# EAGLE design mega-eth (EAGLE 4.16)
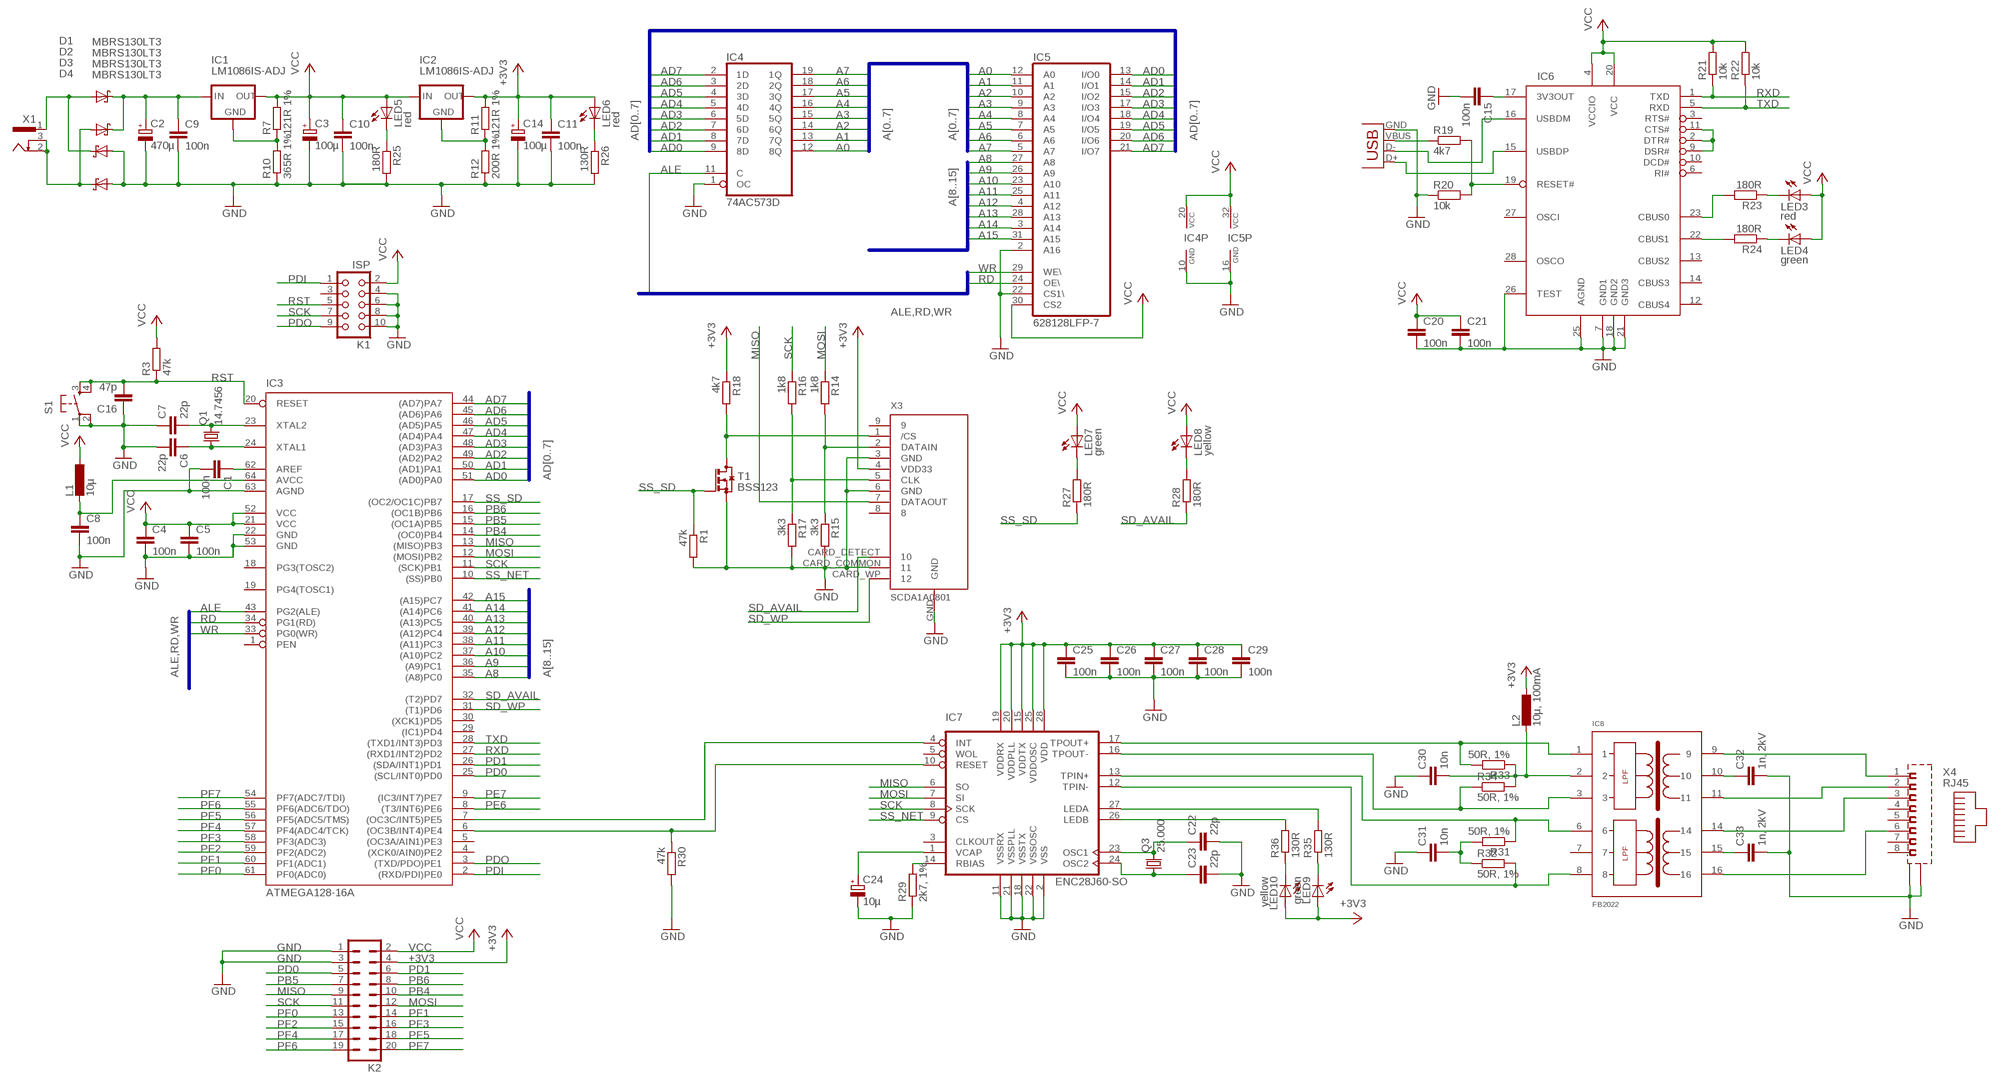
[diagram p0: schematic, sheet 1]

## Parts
C1  100n  C-EUC0805  [C0805]
C2  470µ  CPOL-EU153CLV-0810  [153CLV-0810]
C3  100µ  CPOL-EU153CLV-0605  [153CLV-0605]
C4  100n  C-EUC0805  [C0805]
C5  100n  C-EUC0805  [C0805]
C6  22p  C-EUC0805  [C0805]
C7  22p  C-EUC0805  [C0805]
C8  100n  C-EUC0805  [C0805]
C9  100n  C-EUC0805  [C0805]
C10  100n  C-EUC0805  [C0805]
C11  100n  C-EUC0805  [C0805]
C14  100µ  CPOL-EU153CLV-0605  [153CLV-0605]
C15  100n  C-EUC0805  [C0805]
C16  47p  C-EUC0805  [C0805]
C20  100n  C-EUC0805  [C0805]
C21  100n  C-EUC0805  [C0805]
C22  22p  C-EUC0805  [C0805]
C23  22p  C-EUC0805  [C0805]
C24  10µ  CPOL-EU153CLV-0505  [153CLV-0505]
C25  100n  C-EUC0805  [C0805]
C26  100n  C-EUC0805  [C0805]
C27  100n  C-EUC0805  [C0805]
C28  100n  C-EUC0805  [C0805]
C29  100n  C-EUC0805  [C0805]
C30  10n  C-EUC0805  [C0805]
C31  10n  C-EUC0805  [C0805]
C32  1n, 2kV  C-EU075-032X103  [C075-032X103]
C33  1n, 2kV  C-EU075-032X103  [C075-032X103]
D1  MBRS130LT3  [SMB]
D2  MBRS130LT3  [SMB]
D3  MBRS130LT3  [SMB]
D4  MBRS130LT3  [SMB]
IC1  LM1086IS-ADJ  LM1086TO263  [TO263]
IC2  LM1086IS-ADJ  LM1086TO263  [TO263]
IC3  ATMEGA128-16A  [TQFP64]
IC4  74AC573D  [SO20W]
IC5  628128LFP-7  LP621024CM  [SOP32L]
IC6  FT232RL  [SSOP28DB]
IC7  ENC28J60-SO  [SO28W]
IC8  FB2022  [DIL16/12]
K1  ISP  CON10  [CON10]
K2  MA10-2  [MA10-2]
L1  10µ  L-EUL1206  [L1206]
L2  10µ, 100mA  L-EUL1206  [L1206]
LED3  red  LED3MM  [LED3MM]
LED4  green  LED3MM  [LED3MM]
LED5  red  LED3MM  [LED3MM]
LED6  red  LED3MM  [LED3MM]
LED7  green  LED3MM  [LED3MM]
LED8  yellow  LED3MM  [LED3MM]
LED9  green  LED3MM  [LED3MM]
LED10  yellow  LED3MM  [LED3MM]
Q1  14.7456  CRYTALHC49UP  [HC49UP]
Q3  25.000  CRYTALHC49UP  [HC49UP]
R1  47k  R-EU_R0805  [R0805]
R3  47k  R-EU_R0805  [R0805]
R7  121R 1%  R-EU_R0805  [R0805]
R10  365R 1%  R-EU_R0805  [R0805]
R11  121R 1%  R-EU_R0805  [R0805]
R12  200R 1%  R-EU_R0805  [R0805]
R14  1k8  R-EU_R0805  [R0805]
R15  3k3  R-EU_R0805  [R0805]
R16  1k8  R-EU_R0805  [R0805]
R17  3k3  R-EU_R0805  [R0805]
R18  4k7  R-EU_R0805  [R0805]
R19  4k7  R-EU_R0805  [R0805]
R20  10k  R-EU_R0805  [R0805]
R21  10k  R-EU_R0805  [R0805]
R22  10k  R-EU_R0805  [R0805]
R23  180R  R-EU_R0805  [R0805]
R24  180R  R-EU_R0805  [R0805]
R25  180R  R-EU_R0805  [R0805]
R26  130R  R-EU_R0805  [R0805]
R27  180R  R-EU_R0805  [R0805]
R28  180R  R-EU_R0805  [R0805]
R29  2k7, 1%  R-EU_R0805  [R0805]
R30  47k  R-EU_R0805  [R0805]
R31  50R, 1%  R-EU_R0805  [R0805]
R32  50R, 1%  R-EU_R0805  [R0805]
R33  50R, 1%  R-EU_R0805  [R0805]
R34  50R, 1%  R-EU_R0805  [R0805]
R35  130R  R-EU_R0805  [R0805]
R36  130R  R-EU_R0805  [R0805]
S1  DTSM-6  [DTSM-6]
T1  BSS123  [SOT23]
X1  SCD-014A  [SCD-014-A]
X2  USB-B-H  [USB-B-H]
X3  SCDA1A0801  [SCDA1A0801]
X4  RJ45  [RJ45]

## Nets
+3V3: C11.1 C14.+ C25.1 C26.1 C27.1 C28.1 C29.1 IC2.2(OUT) IC7.15(VDDTX) IC7.19(VDDRX) IC7.20(VDDPLL) IC7.25(VDDOSC) IC7.28(VDD) K2.4 L2.1 LED6.A LED9.A LED10.A R11.2 R18.1 X3.4(VDD33)
A0: IC4.12(8Q) IC5.12(A0)
A1: IC4.13(7Q) IC5.11(A1)
A2: IC4.14(6Q) IC5.10(A2)
A3: IC4.15(5Q) IC5.9(A3)
A4: IC4.16(4Q) IC5.8(A4)
A5: IC4.17(3Q) IC5.7(A5)
A6: IC4.18(2Q) IC5.6(A6)
A7: IC4.19(1Q) IC5.5(A7)
A8: IC3.35((A8)PC0) IC5.27(A8)
A9: IC3.36((A9)PC1) IC5.26(A9)
A10: IC3.37((A10)PC2) IC5.23(A10)
A11: IC3.38((A11)PC3) IC5.25(A11)
A12: IC3.39((A12)PC4) IC5.4(A12)
A13: IC3.40((A13)PC5) IC5.28(A13)
A14: IC3.41((A14)PC6) IC5.3(A14)
A15: IC3.42((A15)PC7) IC5.31(A15)
AD0: IC3.51((AD0)PA0) IC4.9(8D) IC5.13(I/O0)
AD1: IC3.50((AD1)PA1) IC4.8(7D) IC5.14(I/O1)
AD2: IC3.49((AD2)PA2) IC4.7(6D) IC5.15(I/O2)
AD3: IC3.48((AD3)PA3) IC4.6(5D) IC5.17(I/O3)
AD4: IC3.47((AD4)PA4) IC4.5(4D) IC5.18(I/O4)
AD5: IC3.46((AD5)PA5) IC4.4(3D) IC5.19(I/O5)
AD6: IC3.45((AD6)PA6) IC4.3(2D) IC5.20(I/O6)
AD7: IC3.44((AD7)PA7) IC4.2(1D) IC5.21(I/O7)
ALE: IC3.43(PG2(ALE)) IC4.11(C)
GND: C1.2 C2.- C3.- C4.2 C5.2 C6.2 C7.1 C8.2 C9.2 C10.2 C11.2 C14.- C15.2 C16.1 C20.2 C21.2 C22.2 C23.2 C24.- C25.2 C26.2 C27.2 C28.2 C29.2 C30.1 C31.1 C32.2 C33.2 D3.A D4.A IC3.22(GND) IC3.53(GND) IC3.63(AGND) IC4.1(OC) IC4.10(GND) IC5.2(A16) IC5.16(GND) IC5.22(CS1\) IC6.7(GND1) IC6.18(GND2) IC6.21(GND3) IC6.25(AGND) IC6.26(TEST) IC7.2(VSS) IC7.11(VSSRX) IC7.18(VSSTX) IC7.21(VSSPLL) IC7.22(VSSOSC) K1.4 K1.6 K1.8 K1.10 K2.1 K2.3 R1.2 R10.1 R12.1 R15.2 R17.2 R20.1 R25.2 R26.2 R29.1 R30.2 S1.1 S1.2 T1.2(S) X2.GND X3.3(GND) X3.6(GND) X3.CARD_COMMON X3.GND X4.9(GND) X4.10(GND2)
MISO: IC3.13((MISO)PB3) IC7.6(SO) K2.9 X3.7(DATAOUT)
MOSI: IC3.12((MOSI)PB2) IC7.7(SI) K2.12 R14.1
MOSI_3V3: R14.2 R15.1 X3.2(DATAIN)
N$1: IC3.7((OC3C/INT5)PE5) IC7.4(INT)
N$2: IC7.27(LEDA) R35.2
N$3: D1.A D3.C X1.1
N$5: C7.2 IC3.23(XTAL2) Q1.2
N$6: C6.1 IC3.24(XTAL1) Q1.1
N$7: D2.A D4.C X1.2 X1.3
N$9: C1.1 IC3.62(AREF)
N$10: C8.1 IC3.64(AVCC) L1.2
N$11: LED8.K(C) R28.2
N$16: LED7.K(C) R27.2
N$25: C2.+ C9.1 D1.C D2.C IC1.3(IN)
N$29: IC1.1(GND) R7.1 R10.2
N$30: IC2.1(GND) R11.1 R12.2
N$31: IC6.2(DTR#) IC6.9(DSR#) IC6.11(CTS#)
N$32: LED4.K(C) R24.1
N$33: LED3.K(C) R23.1
N$34: IC6.23(CBUS0) R23.2
N$35: LED5.K(C) R25.1
N$36: C15.1 IC6.17(3V3OUT)
N$37: IC6.22(CBUS1) R24.2
N$38: IC6.15(USBDP) X2.D+
N$39: IC6.16(USBDM) X2.D-
N$40: R19.1 X2.VBUS
N$41: IC6.19(RESET#) R19.2 R20.2
N$43: LED6.K(C) R26.1
N$44: C22.1 IC7.23(OSC1) Q3.2
N$47: C23.1 IC7.24(OSC2) Q3.1
N$48: IC7.14(RBIAS) R29.2
N$49: C24.+ IC7.1(VCAP)
N$50: IC7.17(TPOUT+) IC8.1 R33.2
N$51: IC7.16(TPOUT-) IC8.3 R34.1
N$52: IC7.13(TPIN+) IC8.6 R31.1
N$53: IC7.12(TPIN-) IC8.8 R32.2
N$54: C30.2 IC8.2 L2.2 R33.1 R34.2
N$55: C31.2 R31.2 R32.1
N$57: IC7.26(LEDB) R36.2
N$58: LED10.K(C) R36.1
N$59: LED9.K(C) R35.1
N$60: C32.1 IC8.10
N$61: IC3.6((OC3B/INT4)PE4) IC7.10(RESET) R30.1
N$62: IC8.9 X4.1
N$63: IC8.11 X4.2
N$64: IC8.14 X4.3
N$65: IC8.16 X4.6
N$66: C33.1 IC8.15
PB4: IC3.14((OC0)PB4) K2.10
PB5: IC3.15((OC1A)PB5) K2.7
PB6: IC3.16((OC1B)PB6) K2.8
PD0: IC3.25((SCL/INT0)PD0) K2.5
PD1: IC3.26((SDA/INT1)PD1) K2.6
PDI: IC3.2((RXD/PDI)PE0) K1.1
PDO: IC3.3((TXD/PDO)PE1) K1.9
PE6: IC3.8((T3/INT6)PE6)
PE7: IC3.9((IC3/INT7)PE7)
PF0: IC3.61(PF0(ADC0)) K2.13
PF1: IC3.60(PF1(ADC1)) K2.14
PF2: IC3.59(PF2(ADC2)) K2.15
PF3: IC3.58(PF3(ADC3)) K2.16
PF4: IC3.57(PF4(ADC4/TCK)) K2.17
PF5: IC3.56(PF5(ADC5/TMS)) K2.18
PF6: IC3.55(PF6(ADC6/TDO)) K2.19
PF7: IC3.54(PF7(ADC7/TDI)) K2.20
RD: IC3.34(PG1(RD)) IC5.24(OE\)
RST: C16.2 IC3.20(RESET) K1.5 R3.1 S1.3 S1.4
RXD: IC3.27((RXD1/INT2)PD2) IC6.1(TXD) R21.1
SCK: IC3.11((SCK)PB1) IC7.8(SCK) K1.7 K2.11 R16.1
SCK_3V3: R16.2 R17.1 X3.5(CLK)
SD_AVAIL: IC3.32((T2)PD7) R28.1 X3.CARD_DETECT
SD_WP: IC3.31((T1)PD6) X3.CARD_WP
SS_NET: IC3.10((SS)PB0) IC7.9(CS)
SS_SD: IC3.17((OC2/OC1C)PB7) R1.1 R27.1 T1.1(G)
SS_SD_3V3: R18.2 T1.3(D) X3.1(/CS)
TXD: IC3.28((TXD1/INT3)PD3) IC6.5(RXD) R22.1
VCC: C3.+ C4.1 C5.1 C10.1 C20.1 C21.1 IC1.2(OUT) IC2.3(IN) IC3.21(VCC) IC3.52(VCC) IC4.20(VCC) IC5.30(CS2) IC5.32(VCC) IC6.4(VCCIO) IC6.20(VCC) K1.2 K2.2 L1.1 LED3.A LED4.A LED5.A LED7.A LED8.A R3.2 R7.2 R21.2 R22.2
WR: IC3.33(PG0(WR)) IC5.29(WE\)
Unconnected: IC3.1(PEN) IC3.4((XCK0/AIN0)PE2) IC3.5((OC3A/AIN1)PE3) IC3.18(PG3(TOSC2)) IC3.19(PG4(TOSC1)) IC3.29((IC1)PD4) IC3.30((XCK1)PD5) IC5.1(NC) IC6.3(RTS#) IC6.6(RI#) IC6.10(DCD#) IC6.12(CBUS4) IC6.13(CBUS2) IC6.14(CBUS3) IC6.27(OSCI) IC6.28(OSCO) IC7.3(CLKOUT) IC7.5(WOL) IC8.7 K1.3 X3.8 X3.9 X4.4 X4.5 X4.7 X4.8

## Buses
A[8..15]
AD[0..7]
A[0..7]
ALE,RD,WR

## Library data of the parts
C1 C4-C11 C15 C16 C20-C23 C25-C33 = rcl:C-EU: CAPACITOR, European symbol
C2 C3 C14 C24 = rcl:CPOL-EU: POLARIZED CAPACITOR, European symbol
D1-D4 = diode:MBRS130LT3: Schottky Power Rectifier
IC1 IC2 = v-reg-2:LM1086
IC3 = avr:ATMEGA128: MICROCONTROLLER 128 Kbytes FLASH 4 Kbytes SRAM 4 Kbytes EEPROM DUAL USART 8-channel 10 bit ADC
IC4 = 74xx-eu:74*573: 8-bit D latch BUS DRIVER
IC5 = memory:LP621024CM: MEMORY
IC6 = ftdichip-3:FT232RL: USB UART 4th Generation USB UART (USB <-> Serial) Controller
IC7 = microchip-enc28j60:ENC28J60-*: Microchip 10Mbit Eth. contoller with SPI interface
IC8 = fb2022:FB2022: FILTER Bothhand USA, FB2022 10 BaseT Low Pass Filter Transmitter & Receiver http://www.bothhandusa.com Roland Riegel
K1 = con-harting:CON10: CONNECTOR
K2 = con-lstb:MA10-2: PIN HEADER
L1 L2 = rcl:L-EU: INDUCTOR, European symbol
LED3-LED10 = led:LED: LED
Q1 Q3 = crystal:CRYTAL: CRYSTAL
R1 R3 R7 R10-R12 R14-R36 = rcl:R-EU_: RESISTOR, European symbol
S1 = switch-tact:DTSM-6
T1 = transistor-small-signal:BSS123: N-CHANNEL MOS FET
X1 = con-shiua-chyuan:SCD-014A: Power Jack 2.5mm
X2 = con-usb:USB: USB Connectors
X3 = mmc_sd_card:SCDA1A0801
X4 = rj45:RJ45: Reichelt MEBP 8-8G

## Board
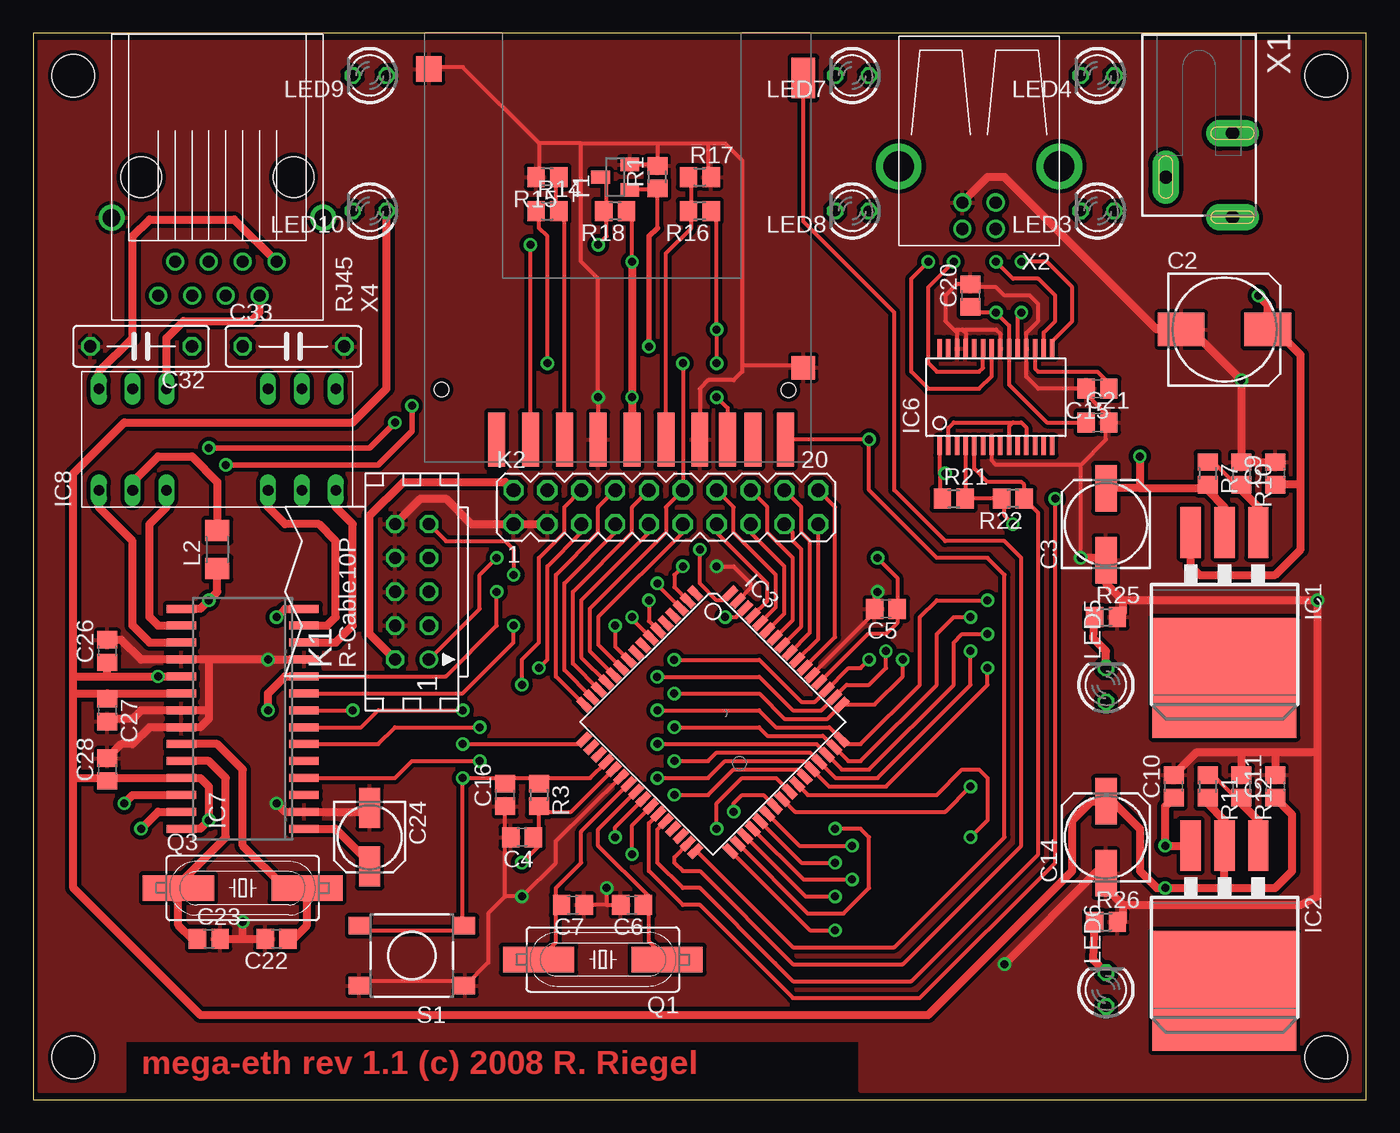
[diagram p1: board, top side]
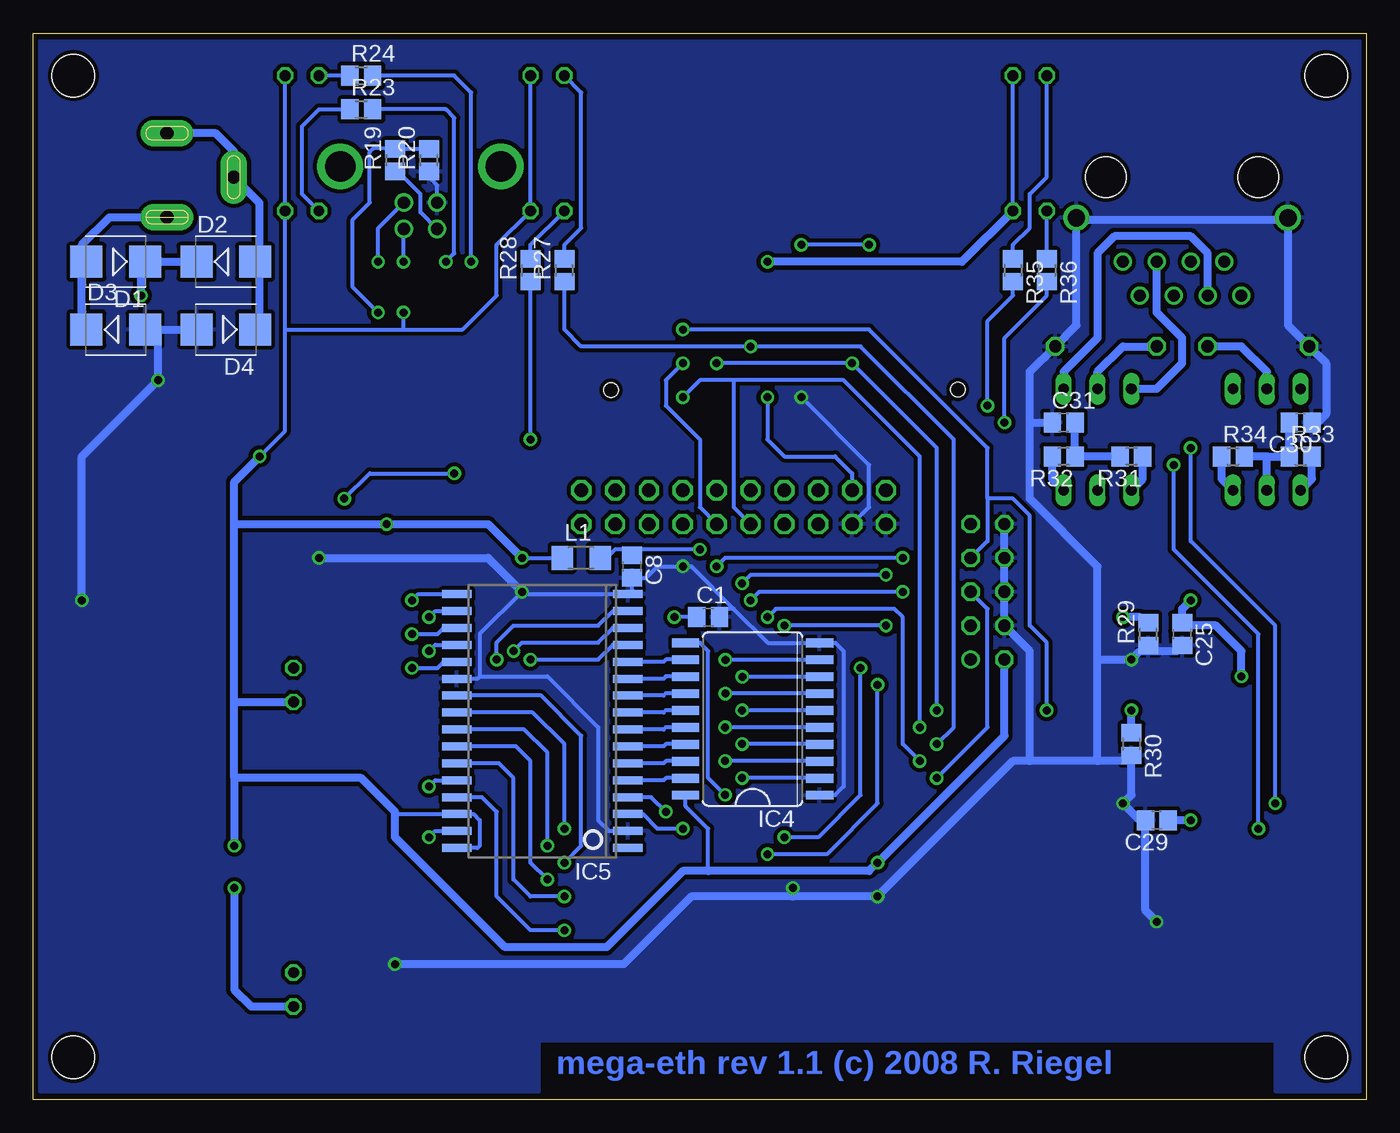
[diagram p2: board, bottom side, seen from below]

Size 100 x 80 mm. Coordinates in mm from the lower left corner, seen from the top.
Outline: 0,0 100,0 100,80 0,80 0,0
Copper layers (1*16): Top 0.035mm / dielectric 1.5mm / Bottom 0.035mm
Design rules "haka_zwilling": minimum track width 8mil, minimum drill 20mil, track to track 8mil, track to pad 8mil, pad to pad 8mil, via to via 8mil, smd to smd 0mil, copper to edge 10mil, drill to drill 10mil, minimum pad ring 8mil, minimum via ring 8mil, stop-mask expansion 4mil, vias tented up to drill 0mil, thermal gap 10mil
Holes 3.2 mm at 3.01,76.83 96.99,3.17 96.99,76.83 3.01,3.17

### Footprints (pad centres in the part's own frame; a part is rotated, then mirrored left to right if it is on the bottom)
C0805 = smd 1.3 x 1.5: 1 -0.85,0; 2 0.85,0
153CLV-0810 = smd 3.5 x 2.5: + 3.25,0; - -3.25,0
153CLV-0605 = smd 3.5 x 1.6: + 2.7,0; - -2.7,0
153CLV-0505 = smd 3 x 1.6: + 2.2,0; - -2.2,0
C075-032X103 = drill 0.914 octagon: 1 -3.81,0; 2 3.81,0
SMB = smd 2.4 x 2.4: A 2.2,0; C -2.2,0
TO263 = smd 1.524 x 3.81: 1 -2.54,-8.255; 2 0,-8.255; 3 2.54,-8.255 | smd 10.8 x 9: 4 0,2.635
TQFP64 = smd 1.194 x 0.559: 1 -7.76,5.905; 2 -7.76,5.118; 3 -7.76,4.331; 4 -7.76,3.543; 5 -7.76,2.756; 6 -7.76,1.968; 7 -7.76,1.181; 8 -7.76,0.394; 9 -7.76,-0.394; 10 -7.76,-1.181; 11 -7.76,-1.968; 12 -7.76,-2.756; 13 -7.76,-3.543; 14 -7.76,-4.331; 15 -7.76,-5.118; 16 -7.76,-5.905; 33 7.76,-5.905; 34 7.76,-5.118; 35 7.76,-4.331; 36 7.76,-3.543; 37 7.76,-2.756; 38 7.76,-1.968; 39 7.76,-1.181; 40 7.76,-0.394; 41 7.76,0.394; 42 7.76,1.181; 43 7.76,1.968; 44 7.76,2.756; 45 7.76,3.543; 46 7.76,4.331; 47 7.76,5.118; 48 7.76,5.905 | smd 0.559 x 1.194: 17 -5.905,-7.76; 18 -5.118,-7.76; 19 -4.331,-7.76; 20 -3.543,-7.76; 21 -2.756,-7.76; 22 -1.968,-7.76; 23 -1.181,-7.76; 24 -0.394,-7.76; 25 0.394,-7.76; 26 1.181,-7.76; 27 1.968,-7.76; 28 2.756,-7.76; 29 3.543,-7.76; 30 4.331,-7.76; 31 5.118,-7.76; 32 5.905,-7.76; 49 5.905,7.76; 50 5.118,7.76; 51 4.331,7.76; 52 3.543,7.76; 53 2.756,7.76; 54 1.968,7.76; 55 1.181,7.76; 56 0.394,7.76; 57 -0.394,7.76; 58 -1.181,7.76; 59 -1.968,7.76; 60 -2.756,7.76; 61 -3.543,7.76; 62 -4.331,7.76; 63 -5.118,7.76; 64 -5.905,7.76
SO20W = smd 0.66 x 2.032: 1 -5.715,-5.029; 2 -4.445,-5.029; 3 -3.175,-5.029; 4 -1.905,-5.029; 5 -0.635,-5.029; 6 0.635,-5.029; 7 1.905,-5.029; 8 3.175,-5.029; 9 4.445,-5.029; 10 5.715,-5.029; 11 5.715,5.029; 12 4.445,5.029; 13 3.175,5.029; 14 1.905,5.029; 15 0.635,5.029; 16 -0.635,5.029; 17 -1.905,5.029; 18 -3.175,5.029; 19 -4.445,5.029; 20 -5.715,5.029
SOP32L = smd 0.6 x 2.2: 1 -9.525,-6.416; 2 -8.255,-6.416; 3 -6.985,-6.416; 4 -5.715,-6.416; 5 -4.445,-6.416; 6 -3.175,-6.416; 7 -1.905,-6.416; 8 -0.635,-6.416; 9 0.635,-6.416; 10 1.905,-6.416; 11 3.175,-6.416; 12 4.445,-6.416; 13 5.715,-6.416; 14 6.985,-6.416; 15 8.255,-6.416; 16 9.525,-6.416; 17 9.525,6.416; 18 8.255,6.416; 19 6.985,6.416; 20 5.715,6.416; 21 4.445,6.416; 22 3.175,6.416; 23 1.905,6.416; 24 0.635,6.416; 25 -0.635,6.416; 26 -1.905,6.416; 27 -3.175,6.416; 28 -4.445,6.416; 29 -5.715,6.416; 30 -6.985,6.416; 31 -8.255,6.416; 32 -9.525,6.416
SSOP28DB = smd 0.348 x 1.397: 1 -4.225,-3.656; 2 -3.575,-3.656; 3 -2.925,-3.656; 4 -2.275,-3.656; 5 -1.625,-3.656; 6 -0.975,-3.656; 7 -0.325,-3.656; 8 0.325,-3.656; 9 0.975,-3.656; 10 1.625,-3.656; 11 2.275,-3.656; 12 2.925,-3.656; 13 3.575,-3.656; 14 4.225,-3.656; 15 4.225,3.656; 16 3.575,3.656; 17 2.925,3.656; 18 2.275,3.656; 19 1.625,3.656; 20 0.975,3.656; 21 0.325,3.656; 22 -0.325,3.656; 23 -0.975,3.656; 24 -1.625,3.656; 25 -2.275,3.656; 26 -2.925,3.656; 27 -3.575,3.656; 28 -4.225,3.656
SO28W = smd 0.6 x 2.2: 1 -8.255,-4.6; 2 -6.985,-4.6; 3 -5.715,-4.6; 4 -4.445,-4.6; 5 -3.175,-4.6; 6 -1.905,-4.6; 7 -0.635,-4.6; 8 0.635,-4.6; 9 1.905,-4.6; 10 3.175,-4.6; 11 4.445,-4.6; 12 5.715,-4.6; 13 6.985,-4.6; 14 8.255,-4.6; 15 8.255,4.6; 16 6.985,4.6; 17 5.715,4.6; 18 4.445,4.6; 19 3.175,4.6; 20 1.905,4.6; 21 0.635,4.6; 22 -0.635,4.6; 23 -1.905,4.6; 24 -3.175,4.6; 25 -4.445,4.6; 26 -5.715,4.6; 27 -6.985,4.6; 28 -8.255,4.6
DIL16/12 = drill 0.8 long: 1 0,0; 2 2.54,0; 3 5.08,0; 6 12.7,0; 7 15.24,0; 8 17.78,0; 9 0,7.62; 10 2.54,7.62; 11 5.08,7.62; 14 12.7,7.62; 15 15.24,7.62; 16 17.78,7.62
CON10 = drill 0.914 round: 1 -5.08,-1.27 | drill 0.914 octagon: 2 -5.08,1.27; 3 -2.54,-1.27; 4 -2.54,1.27; 5 0,-1.27; 6 0,1.27; 7 2.54,-1.27; 8 2.54,1.27; 9 5.08,-1.27; 10 5.08,1.27
MA10-2 = drill 1.016 octagon: 1 -11.43,-1.27; 2 -11.43,1.27; 3 -8.89,-1.27; 4 -8.89,1.27; 5 -6.35,-1.27; 6 -6.35,1.27; 7 -3.81,-1.27; 8 -3.81,1.27; 9 -1.27,-1.27; 10 -1.27,1.27; 11 1.27,-1.27; 12 1.27,1.27; 13 3.81,-1.27; 14 3.81,1.27; 15 6.35,-1.27; 16 6.35,1.27; 17 8.89,-1.27; 18 8.89,1.27; 19 11.43,-1.27; 20 11.43,1.27
L1206 = smd 1.6 x 1.803: 1 -1.422,0; 2 1.422,0
LED3MM = drill 0.813 octagon: A -1.27,0; K 1.27,0
HC49UP = smd 5.334 x 1.93: 1 -4.826,0; 2 4.826,0
R0805 = smd 1.3 x 1.5: 1 -0.85,0; 2 0.85,0
DTSM-6 = smd 1.55 x 1.3: 1 -3.975,2.25; 2 3.975,2.25; 3 -3.975,-2.25; 4 3.975,-2.25
SOT23 = smd 1 x 1.4: 1 -0.95,-1.1; 2 0.95,-1.1; 3 0,1.1
SCD-014-A = drill 1 pad 2 long: 1 -2.5,13.8; 2 -2.5,7.5; 3 2.5,10.8
USB-B-H = drill 0.914 round: D+ 0,1.25; D- 1.981,1.25; GND 0,-1.25; VBUS 1.981,-1.25 | drill 2.286 round: P$1 -2.718,-6.02; P$2 -2.718,6.02
SCDA1A0801 = smd 1.27 x 4.064: 1 6.35,13.97; 2 3.81,13.97; 3 1.27,13.97; 4 -1.27,13.97; 5 -3.81,13.97; 6 -6.35,13.97; 7 -8.433,13.97; 8 -10.338,13.97; 9 8.89,13.97; CARD_DETECT -12.776,13.97 | smd 1.778 x 1.778: CARD_COMMON -14.122,8.585 | smd 1.778 x 3.048: CARD_WP -14.122,-13.157 | smd 1.905 x 1.905: GND 13.97,-13.818 | hole 1.1: 13.005,10.236; -13.005,10.262
RJ45 = drill 0.9 round: 1 1.27,6.35; 2 2.54,8.89; 3 3.81,6.35; 4 5.08,8.89; 5 6.35,6.35; 6 7.62,8.89; 7 8.89,6.35; 8 10.16,8.89 | drill 1.3 round: 9 -2.223,3.048; 10 13.652,3.048 | hole 3.048: 0,0; 11.43,0

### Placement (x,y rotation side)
C1  49.37,36.19 0 bottom
C2  89.37,57.78 0 top
C3  80.48,43.18 90 top
C4  36.66,19.68 180 top
C5  63.97,36.83 180 top
C6  44.92,14.6 180 top
C7  40.48,14.6 180 top
C8  55.08,40 270 bottom
C9  93.18,46.98 90 top
C10  85.56,23.49 90 top
C11  93.18,23.49 90 top
C14  80.48,19.68 90 top
C15  79.84,53.34 180 top
C16  35.39,22.86 90 top
C20  70.32,60.32 90 top
C21  79.84,50.8 0 top
C22  18.25,12.06 180 top
C23  13.17,12.06 0 top
C24  25.23,19.68 270 top
C25  13.81,34.92 270 bottom
C26  5.55,33.65 90 top
C27  5.55,29.2 270 top
C28  5.55,24.76 90 top
C29  15.71,20.95 180 bottom
C30  4.92,50.8 180 bottom
C31  22.7,50.8 0 bottom
C32  8.09,56.51 180 top
C33  19.52,56.51 0 top
D1  93.81,62.86 180 bottom
D2  85.56,62.86 0 bottom
D3  93.81,57.78 0 bottom
D4  85.56,57.78 180 bottom
IC1  89.37,34.29 180 top
IC2  89.37,10.79 180 top
IC3  50.98,28.31 315 top
IC4  46.03,28.55 90 bottom
IC5  61.81,28.4 90 bottom
IC6  72.22,52.7 0 top
IC7  15.71,28.57 90 top
IC8  4.92,45.72 0 top
K1  28.41,38.1 90 top
K2  47.46,44.45 0 top
L1  58.89,40.64 0 bottom
L2  13.81,41.27 90 top
LED3  79.84,66.67 180 top
LED4  79.84,76.83 180 top
LED5  80.48,31.11 90 top
LED6  80.48,8.25 90 top
LED7  61.43,76.83 180 top
LED8  61.43,66.67 180 top
LED9  25.23,76.83 180 top
LED10  25.23,66.67 180 top
Q1  42.73,10.51 180 top
Q3  15.71,15.87 0 top
R1  46.82,69.21 90 top
R3  37.94,22.86 270 top
R7  88.1,46.98 270 top
R10  90.64,46.98 270 top
R11  88.1,23.49 270 top
R12  90.64,23.49 270 top
R14  38.57,66.67 0 top
R15  38.57,69.21 180 top
R16  50,66.67 180 top
R17  50,69.21 0 top
R18  43.65,66.67 180 top
R19  72.86,70.48 90 bottom
R20  70.32,70.48 90 bottom
R21  69.05,45.08 0 top
R22  73.5,45.08 180 top
R23  75.4,74.29 0 bottom
R24  75.4,76.83 0 bottom
R25  80.48,36.19 0 top
R26  80.48,13.33 0 top
R27  60.16,62.23 90 bottom
R28  62.7,62.23 90 bottom
R29  16.34,34.92 90 bottom
R30  17.61,26.66 270 bottom
R31  17.61,48.26 180 bottom
R32  22.7,48.26 180 bottom
R33  4.92,48.26 0 bottom
R34  10,48.26 0 bottom
R35  26.5,62.23 270 bottom
R36  23.96,62.23 270 bottom
S1  28.41,10.79 180 top
T1  43.65,69.21 90 top
X1  87.47,80 180 top
X2  70.95,67.3 270 top
X3  43.65,63.5 180 top
X4  19.52,69.21 180 top

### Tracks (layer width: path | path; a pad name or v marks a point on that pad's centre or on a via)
+3V3  (via drill 0.6)
  Top 0.305: R18.1 44.92,66.67 v44.92,62.86
  Top 0.61: R11.2 88.1,22.22 89.37,20.95 IC2.2 89.37,15.87 | 89.37,15.87 v84.92,15.87 84.29,15.87 83.02,17.14 83.02,20.31 81.11,22.22 80.48,22.22 C14.+ 79.37,22.38 77.94,20.95 77.94,17.14 67.14,6.34 12.54,6.34 3.01,15.87 3.01,24.12 | X3.4 v44.92,52.7 v44.92,62.86 | IC7.28 12.54,20.31 v13.17,20.95 13.17,23.49 12.54,24.12 IC7.25 5.55,24.12 | IC7.15 12.54,36.83 v13.17,37.46 13.81,38.1 L2.1 | 3.01,24.12 3.01,30.47 | 3.01,30.47 3.01,31.74 | 3.01,31.74 5.55,31.74 | 5.55,31.74 v9.36,31.74 IC7.19 | 5.55,31.74 C26.1 | 3.01,30.47 5.55,30.47 | 5.55,30.47 IC7.20 | 5.55,30.47 C27.1 | 3.01,31.74 3.01,46.98 6.82,50.8 23.96,50.8 26.5,53.34 LED10.A | 3.01,24.12 5.55,24.12 | 5.55,24.12 C28.1 | C11.1 94.45,21.37 94.45,17.14 93.18,15.87 89.37,15.87
  Bottom 0.305: LED10.A LED9.A | K2.4 38.57,46.98 39.84,48.26 43.65,48.26 X3.4 v44.92,52.7
  Bottom 0.61: LED6.A 83.66,6.98 84.92,8.25 v84.92,15.87 | v13.17,37.46 13.81,36.83 C25.1 13.81,35.55 11.27,35.55 9.36,33.65 v9.36,31.74 | v44.92,62.86 30.31,62.86 LED10.A | v13.17,20.95 C29.1
A0
  Bottom 0.305: IC4.12 51.06,33.02 52.54,33.02 52.71,32.85 IC5.12
A1
  Bottom 0.305: IC4.13 51.06,31.74 52.54,31.74 52.71,31.57 IC5.11
A2
  Bottom 0.305: IC4.14 51.06,30.47 52.54,30.47 52.71,30.3 IC5.10
A3
  Bottom 0.305: IC4.15 51.06,29.2 52.54,29.2 52.71,29.04 IC5.9
A4
  Bottom 0.305: IC4.16 51.06,27.93 52.54,27.93 52.71,27.77 IC5.8
A5
  Bottom 0.305: IC4.17 51.06,26.66 52.54,26.66 52.71,26.49 IC5.7
A6
  Bottom 0.305: IC4.18 51.06,25.39 52.54,25.39 52.71,25.22 IC5.6
A7
  Bottom 0.305: IC4.19 51.06,24.12 52.54,24.12 52.71,23.95 IC5.5
A8  (via drill 0.6)
  Top 0.305: IC3.35 57.94,15.24 v60.16,15.24
  Bottom 0.305: IC5.27 65.07,25.22 63.97,24.12 63.97,16.5 62.7,15.24 v60.16,15.24
A9  (via drill 0.6)
  Top 0.305: IC3.36 57.78,16.5 v61.43,16.5
  Bottom 0.305: IC5.26 63.8,26.49 62.7,25.39 62.7,17.77 v61.43,16.5
A10  (via drill 0.6)
  Top 0.305: IC3.37 57.63,17.77 v60.16,17.77
  Bottom 0.305: IC5.23 61.89,30.3 58.89,27.3 58.89,19.04 v60.16,17.77
A11  (via drill 0.6)
  Top 0.305: IC3.38 57.47,19.04 v61.43,19.04
  Bottom 0.305: IC5.25 63.16,27.77 61.43,26.03 v61.43,19.04
A12  (via drill 0.6)
  Top 0.305: v52.54,21.58 52.54,22.22 53.17,22.86 54.77,22.86 IC3.39
  Bottom 0.305: 54.91,22.68 IC5.4 53.64,22.68 v52.54,21.58
A13  (via drill 0.6)
  Top 0.305: IC3.40 57.16,21.58 68.41,21.58 v70.32,23.49
  Bottom 0.305: IC5.28 69.86,23.95 v70.32,23.49
A14  (via drill 0.6)
  Top 0.305: IC3.41 55.73,24.12 53.17,24.12 51.27,22.22 v51.27,20.31
  Bottom 0.305: IC5.3 54.27,21.41 53.17,20.31 v51.27,20.31
A15  (via drill 0.6)
  Top 0.305: IC3.42 58.12,22.86 67.78,22.86 69.69,24.76 70.95,24.76 71.59,24.12 71.59,20.95 v70.32,19.68
  Bottom 0.305: IC5.31 69.86,20.14 v70.32,19.68
AD0  (via drill 0.6)
  Top 0.305: v48.07,33 54.46,33 57.62,29.84 58.63,29.84 IC3.51 61.17,32.38 62.06,32.38 v62.7,33.02
  Bottom 0.305: IC4.9 v48.07,33 | IC5.13 56.52,34.12 57.62,33.02 v62.7,33.02
AD1  (via drill 0.6)
  Top 0.305: v46.8,31.72 54.46,31.72 56.98,29.2 59.11,29.2 IC3.50 61.02,31.11 62.7,31.11 63.97,32.38 v63.97,33.65
  Bottom 0.305: IC4.8 v46.8,31.72 | v63.97,33.65 63.34,34.29 57.62,34.29 56.52,35.39 IC5.14
AD2  (via drill 0.6)
  Top 0.305: v48.07,30.45 54.46,30.45 56.35,28.57 59.59,28.57 IC3.49 63.12,29.63 65.24,31.74 v65.24,33.02
  Bottom 0.305: IC4.7 v48.07,30.45 | v65.24,33.02 65.24,34.29 63.97,35.55 57.62,35.55 56.52,36.66 IC5.15
AD3  (via drill 0.6)
  Top 0.305: v46.82,29.2 54.45,29.2 55.71,27.93 59.72,27.93 IC3.48 60.99,26.66 62.06,26.66 66.51,31.11 66.51,36.19 67.78,37.46 v71.59,37.46
  Bottom 0.305: IC4.6 41.02,29.2 v46.82,29.2 | IC5.17 71.12,37.93 v71.59,37.46
AD4  (via drill 0.6)
  Top 0.305: v48.09,27.93 54.45,27.93 55.08,27.3 59.24,27.3 IC3.47 61.14,25.39 62.06,25.39 67.78,31.11 67.78,34.92 69.05,36.19 v70.32,36.19
  Bottom 0.305: IC4.5 41.02,27.93 v48.09,27.93 | IC5.18 69.86,36.66 v70.32,36.19
AD5  (via drill 0.6)
  Top 0.305: v46.82,26.66 58.76,26.66 IC3.46 60.66,24.76 62.7,24.76 69.05,31.11 69.05,34.29 69.69,34.92 v71.59,34.92
  Bottom 0.305: 41.02,26.66 v46.82,26.66 | IC5.19 69.22,35.39 69.69,34.92 v71.59,34.92
  Bottom 0.406: IC4.4 41.02,26.66
AD6  (via drill 0.6)
  Top 0.305: v48.09,25.39 50.63,25.39 51.27,26.03 58.28,26.03 IC3.45 60.19,24.12 63.34,24.12 70.32,31.11 v70.32,33.65
  Bottom 0.305: 41.02,25.39 v48.09,25.39 | IC5.20 69.86,34.12 v70.32,33.65
  Bottom 0.406: IC4.3 41.02,25.39
AD7  (via drill 0.6)
  Top 0.305: v46.82,24.12 50.63,24.12 51.91,25.39 57.8,25.39 IC3.44 59.71,23.49 63.97,23.49 71.59,31.11 v71.59,32.38
  Bottom 0.305: IC4.2 41.02,24.12 v46.82,24.12 | IC5.21 69.22,32.85 69.69,32.38 v71.59,32.38
ALE  (via drill 0.6)
  Top 0.305: IC3.43 57.32,24.76 52.54,24.76 50.63,22.86 v48.09,22.86
  Bottom 0.305: IC4.11 49.98,34.27 49.37,33.65 49.37,24.12 v48.09,22.86
GND  (via drill 0.6)
  Top 0.305: IC6.21 72.55,57.46 72.22,57.78 69.69,57.78 | IC6.7 71.9,47.95 72.22,47.62 78.58,47.62 | 78.58,47.62 80.48,49.53 80.48,50.8 80.48,51.43 79,52.91 C15.2 75.4,53.34 74.5,54.23 IC6.18 74.5,57.52 75.4,58.41 75.4,59.69 74.77,60.32 72.86,60.32 72.22,60.96 70.32,60.96 C20.2 69.27,61.17 68.41,60.32 68.41,58.41 69.05,57.78 | 69.05,57.78 69.69,57.78 | IC6.26 69.3,57.53 69.05,57.78 | IC6.25 69.95,57.52 69.69,57.78 | v78.58,40.64 78.58,47.62 | X3.3 v42.38,52.7 42.38,61.59 41.11,62.86 41.11,71.75 | 50.63,71.75 51.91,71.75 53.17,70.48 53.17,55.24 | 41.11,71.75 37.94,71.75 | R15.2 37.94,69.42 37.94,71.75 | R17.2 50.63,69.42 50.63,71.75 | 41.11,71.75 46.82,71.75 | 46.82,71.75 50.63,71.75 | IC3.63 53.81,38.38 53.81,38.73 52.54,40 v51.27,40 | IC3.22 39.2,19.41 39.2,17.77 v36.66,15.24 35.39,15.24 | 35.39,19.68 C16.1 | 35.39,19.68 C4.2 | 35.39,15.24 35.39,19.68 | 43.02,14.6 C7.1 | 43.02,14.6 C6.2 | S1.2 24.78,8.89 32.22,8.89 32.22,8.71 S1.1 34.12,10.28 34.12,13.97 35.39,15.24 | IC3.53 62.7,36.13 62.7,36.19 C5.2 63.12,37.88 v63.34,38.1 | 46.82,71.75 46.82,70.48 | 46.82,70.48 R1.2 | T1.2 46.5,70.16 46.82,70.48 | X3.6 50,53.34 50.63,53.97 52.54,53.97 53.17,54.61 53.17,55.24 | 57.77,55.09 53.33,55.09 53.17,55.24 | v43.02,15.87 43.02,14.6 | X3.GND 29.68,77.46 32.22,77.46 37.94,71.75
  Top 0.406: 80.48,50.8 C21.2 | 57.77,55.09 X3.CARD_COMMON 57.77,54.76
  Top 0.61: 81.75,37.46 v96.36,37.46 96.36,26.03 | R25.2 81.75,36.51 81.75,37.46 | 81.75,37.46 80.48,38.73 C3.- 80.32,40.64 v78.58,40.64 | 81.75,14.6 80.48,15.87 C14.- 80.48,17.14 79.84,17.14 v72.86,10.16 | R26.2 81.75,13.33 81.75,14.6 | 96.36,26.03 96.36,15.24 95.08,14.6 81.75,14.6 | C26.2 6.6,34.5 8.09,33.02 IC7.18 13.17,33.02 | C27.2 5.76,28.57 7.46,28.57 8.09,29.2 IC7.21 13.17,29.2 | C28.2 6.6,26.66 7.46,26.66 8.73,27.93 IC7.22 12.54,27.93 13.17,28.57 13.17,29.2 | C23.2 15.71,12.06 | 15.71,12.06 C22.2 | v18.25,22.22 18.88,21.58 IC7.2 25.23,21.58 C24.- | IC7.11 v17.61,33.02 13.17,33.02 | 13.17,33.02 13.17,29.2 | K1.10 29.04,45.08 30.95,45.08 32.85,43.18 K2.1 K2.3 | 15.71,12.06 v15.71,13.33 | C10.2 87.25,26.03 90.64,26.03 | 96.36,26.03 93.18,26.03 | 93.18,26.03 90.64,26.03 | 90.64,26.03 R12.1 | 93.18,26.03 C11.2 | X2.GND 69.7,67.32 71.59,69.21 72.86,69.21 84.29,57.78 86.19,57.78 | 86.19,57.78 C2.- | 86.19,57.78 86.83,57.78 v90.64,53.97 R10.1 92.97,47.84 93.18,47.62 C9.2
  Bottom 0.305: R20.1 70.32,69.21 69.7,68.59 X2.GND | 63.16,37.93 IC5.16 55.08,38.24 C8.2 54.02,39.15 53.17,40 v51.27,40 50.63,40 47.46,36.83 | K2.3 37.3,44.45 37.3,47.62 v42.38,52.7 | IC5.22 66.68,31.57 66.51,31.74 | 66.51,31.74 66.51,34.92 v63.34,38.1 | IC4.1 41.09,22.83 41.11,22.86 39.84,22.86 39.2,23.49 39.2,33.65 39.82,34.27 IC4.10 44.9,34.27 47.46,36.83 | IC5.2 56.81,20.14 57.62,20.95 57.62,27.93 61.43,31.74 66.51,31.74 | C1.2 47.88,36.83 47.46,36.83
  Bottom 0.406: v63.34,38.1 63.16,37.93 | 43.02,15.24 v43.02,15.87
  Bottom 0.61: K1.10 K1.8 K1.6 K1.4 25.23,33.65 25.23,25.39 | v72.86,10.16 55.71,10.16 50.63,15.24 43.02,15.24 v36.66,15.24 26.5,25.39 25.23,25.39 | v78.58,40.64 65.88,40.64 v63.34,38.1 | 17.61,25.39 17.61,22.86 v18.25,22.22 16.98,20.95 C29.2 16.56,14.18 v15.71,13.33 | 16.34,33.65 16.98,33.65 v17.61,33.02 20.15,33.02 | 16.34,33.65 R29.1 | C25.2 14.23,33.65 16.34,33.65 | 20.15,25.39 25.23,25.39 | 20.15,25.39 20.15,33.02 | 17.61,25.39 R30.2 | 17.61,25.39 20.15,25.39 | X4.9 21.74,58.1 C33.2 25.23,54.61 25.23,50.8 | C30.1 3.64,50.8 3.01,51.43 3.01,55.24 C32.2 5.87,58.1 X4.10 5.87,66.35 6.18,66.03 21.61,66.03 X4.9 | 25.23,50.8 25.23,45.08 20.15,40 20.15,33.02 | 25.23,50.8 C31.1 | X4.9 21.74,66.35 | 90.64,57.78 D4.A | 90.64,57.78 D3.A | 90.64,57.78 v90.64,53.97 96.36,48.26 v96.36,37.46
  pour Top (isolate 0.305): 0.47,79.37 99.53,79.37 99.53,0.63 62.06,0.63 62.06,4.44 6.82,4.44 6.82,0.63 0.47,0.63
  pour Bottom (isolate 0.305): 0.47,79.37 99.53,79.37 99.53,0.63 62.06,0.63 62.06,4.44 6.82,4.44 6.82,0.63 0.47,0.63
MISO  (via drill 0.6)
  Top 0.305: IC7.6 25.87,26.66 27.14,27.93 v33.49,27.93 | v51.27,52.7 52.08,51.89 X3.7 | IC3.13 41.11,33.18 41.11,37.46 46.19,42.54 K2.9
  Bottom 0.305: 47.46,53.97 50,53.97 v51.27,52.7 | 47.46,53.97 39.2,53.97 33.49,48.26 v33.49,27.93 | K2.9 47.46,44.45 47.46,53.97
MOSI  (via drill 0.6)
  Top 0.305: IC7.7 24.6,27.93 25.87,29.2 v32.22,29.2 | R14.1 37.94,66.67 37.94,65.4 38.57,64.77 v38.57,55.24 | IC3.12 41.74,33.66 41.74,36.83 47.46,42.54 47.46,44.45 K2.12 v48.73,55.24
  Bottom 0.305: v32.22,29.2 32.22,48.89 v38.57,55.24 v48.73,55.24
MOSI_3V3
  Top 0.305: X3.2 39.84,66.03 39.2,66.67 | 39.2,66.67 R14.2 | R15.1 39.2,68.89 39.2,66.67
N$1  (via drill 0.6)
  Top 0.305: IC7.4 27.14,24.12 28.41,25.39 v33.49,25.39 | IC3.7 44.92,36.05 v44.92,36.19
  Bottom 0.305: v33.49,25.39 34.76,26.66 34.76,36.19 35.39,36.83 44.28,36.83 v44.92,36.19
N$2  (via drill 0.6)
  Top 0.406: v14.44,47.62 25.87,47.62 28.41,50.16 v28.41,52.07
  Top 0.61: IC7.27 9.36,21.58 v8.09,20.31
  Bottom 0.305: v8.09,20.31 8.09,34.92 14.44,41.27 v14.44,47.62 | v28.41,52.07 28.41,58.41 26.5,60.32 R35.2
N$3
  Bottom 0.61: X1.1 94.28,66.2 96.36,64.13 96.36,62.86 | D3.C 96.36,57.78 96.36,62.86 | 96.36,62.86 D1.A
N$5
  Top 0.305: IC3.23 41.11,20.11 41.11,17.77 39.2,15.87 39.2,14.6 | Q1.2 39.2,11.81 39.2,14.6 | 39.2,14.6 C7.2
N$6
  Top 0.305: IC3.24 42.38,20.27 42.38,19.04 46.19,15.24 46.19,14.6 | Q1.1 46.19,11.87 46.19,14.6 | 46.19,14.6 C6.1
N$7
  Bottom 0.61: X1.2 86.31,72.5 84.97,71.16 X1.3 83.02,67.26 83.02,62.86 | D4.C 83.02,57.78 83.02,62.86 | 83.02,62.86 D2.A
N$9  (via drill 0.6)
  Top 0.305: IC3.62 52.73,36.19 v51.91,36.19
  Bottom 0.305: C1.1 v51.91,36.19
N$10  (via drill 0.6)
  Top 0.305: IC3.64 51.78,37.46 51.27,37.46 50,38.73 v50,41.27
  Bottom 0.305: v50,41.27 55.08,41.27 | 55.08,41.27 56.35,41.27 56.98,40.64 L1.2 | 55.08,41.27 C8.1
N$11
  Bottom 0.305: R28.2 62.7,64.13 LED8.K
N$16
  Bottom 0.305: R27.2 60.16,64.13 58.89,65.4 58.89,75.56 LED7.K
N$25  (via drill 0.6)
  Top 0.61: IC1.3 86.83,40 87.47,39.37 93.18,39.37 95.08,41.27 95.08,46.35 | C9.1 94.87,46.14 95.08,46.35 | 95.08,46.35 95.08,55.88 93.18,57.78 C2.+ 92.62,59.61 v91.91,60.32
  Bottom 0.61: D2.C D1.C 91.91,62.86 v91.91,60.32
N$29
  Top 0.305: R7.1 88.42,47.94 90.64,45.72 R10.2
  Top 0.61: IC1.1 91.91,44.45 90.64,45.72
N$30
  Top 0.305: R11.1 88.42,24.44 90.64,22.22 R12.2
  Top 0.61: IC2.1 91.91,20.95 90.64,22.22
N$31
  Top 0.305: IC6.2 68.65,50.4 69.05,50.8 73.5,50.8 | 73.5,50.8 74.13,50.8 74.5,50.43 IC6.11 | IC6.9 73.2,50.5 73.5,50.8
N$32
  Bottom 0.305: R24.1 LED4.K
N$33
  Bottom 0.305: R23.1 78.58,74.29 79.84,73.02 79.84,67.94 LED3.K
N$34  (via drill 0.6)
  Top 0.305: IC6.23 71.25,54.9 70.95,54.61 67.78,54.61 67.14,55.24 67.14,60.96 v69.05,62.86
  Bottom 0.305: R23.2 69.05,74.29 68.41,73.66 68.41,63.5 v69.05,62.86
N$35
  Top 0.61: R25.1 79.53,34.6 80.48,33.65 LED5.K
N$36
  Top 0.305: IC6.17 75.15,54.86 75.4,54.61 79.84,54.61 80.48,53.97 80.48,53.34
  Top 0.406: 80.48,53.34 C15.1
N$37  (via drill 0.6)
  Top 0.305: IC6.22 71.9,54.28 70.95,53.34 67.14,53.34 65.88,54.61 65.88,61.59 v67.14,62.86
  Bottom 0.305: R24.2 68.41,76.83 67.14,75.56 v67.14,62.86
N$38  (via drill 0.6)
  Top 0.305: IC6.15 76.45,56.93 77.94,58.41 77.94,60.96 76.03,62.86 v74.13,62.86
  Bottom 0.305: X2.D+ 72.22,67.3 74.13,65.4 v74.13,62.86
N$39  (via drill 0.6)
  Top 0.305: v72.22,62.86 73.5,61.59 75.4,61.59 76.67,60.32 76.67,58.41 75.8,57.55 IC6.16
  Bottom 0.305: X2.D- 72.22,65.3 v72.22,62.86
N$40
  Bottom 0.305: X2.VBUS 70.95,66.57 70.95,67.94 72.55,69.53 R19.1
N$41  (via drill 0.6)
  Top 0.305: IC6.19 73.85,58.77 v74.13,59.05
  Bottom 0.305: v74.13,59.05 76.03,60.96 76.03,66.03 74.77,67.3 74.77,71.11 74.45,71.43 R19.2 | R19.2 R20.2 | R19.2 72.86,71.11
N$43
  Top 0.61: R26.1 79.53,10.47 LED6.K
N$44
  Top 0.61: IC7.23 13.81,26.66 15.71,24.76 15.71,19.04 18.88,15.87 Q3.2 20.54,13.08 19.52,12.06 C22.1
N$47
  Top 0.61: IC7.24 13.17,25.39 14.44,24.12 14.44,19.68 10.88,16.12 Q3.1 10.88,13.08 11.9,12.06 C23.1
N$48  (via drill 0.6)
  Top 0.61: IC7.14 18.88,36.83 v18.25,36.19
  Bottom 0.61: R29.2 16.34,35.55 16.98,36.19 v18.25,36.19
N$49
  Top 0.61: C24.+ 25.23,17.77 22.7,20.31 IC7.1
N$50
  Top 0.61: IC8.1 4.92,44.45 7.46,41.91 7.46,35.55 8.73,34.29 IC7.17
  Bottom 0.61: R33.2 4.07,46.57 IC8.1
N$51
  Top 0.61: IC8.3 10,44.45 8.73,43.18 8.73,36.19 9.36,35.55 IC7.16
  Bottom 0.61: R34.1 10.85,46.57 IC8.3
N$52
  Top 0.61: IC8.6 17.61,44.45 18.88,43.18 21.42,43.18 22.7,41.91 22.7,36.19 22.06,35.55 IC7.13
  Bottom 0.61: R31.1 16.77,46.57 IC8.6
N$53
  Top 0.61: IC8.8 22.7,44.45 23.96,43.18 23.96,35.55 22.7,34.29 IC7.12
  Bottom 0.61: R32.2 23.54,46.57 IC8.8
N$54
  Top 0.61: IC8.2 7.46,46.35 9.36,48.26 11.9,48.26 13.81,46.35 L2.2
  Bottom 0.61: 7.46,48.26 6.18,48.26 | 7.46,48.26 R34.2 | 5.55,48.26 R33.1 6.18,48.26 | IC8.2 7.46,48.26 | C30.2 5.76,48.68 6.18,48.26
N$55
  Bottom 0.61: 21.42,48.26 R31.2 18.25,48.26 | 21.42,48.26 R32.1 | C31.2 21.84,48.68 21.42,48.26
N$57  (via drill 0.6)
  Top 0.406: v13.17,48.89 25.23,48.89 v27.14,50.8
  Top 0.61: IC7.26 7.46,22.86 v6.82,22.22
  Bottom 0.305: v6.82,22.22 6.82,35.55 13.17,41.91 v13.17,48.89 | v27.14,50.8 27.14,57.15 23.96,60.32 R36.2
N$58
  Bottom 0.305: R36.1 LED10.K
N$59
  Bottom 0.305: LED9.K 23.96,69.21 25.23,67.94 25.23,65.4 26.5,64.13 R35.1
N$60
  Bottom 0.61: IC8.10 7.46,54.61 9.36,56.51 C32.1
N$61  (via drill 0.6)
  Top 0.305: IC7.10 30.95,31.74 34.76,35.55 v34.76,38.1 | IC3.6 46.19,35.89 v46.19,37.46
  Top 0.61: IC7.10 18.88,31.74 17.61,30.47 v17.61,29.2
  Bottom 0.305: v34.76,38.1 45.55,38.1 v46.19,37.46
  Bottom 0.61: R30.1 v17.61,29.2
N$62
  Top 0.61: IC8.9 4.92,54.61 7.46,57.15 7.46,64.77 8.73,66.03 15.08,66.03 X4.1
N$63
  Top 0.61: IC8.11 10,57.15 11.27,58.41 16.34,58.41 16.98,59.05 X4.2
N$64
  Bottom 0.61: IC8.14 15.71,53.34 13.81,55.24 13.81,57.15 15.71,59.05 X4.3
N$65
  Bottom 0.61: IC8.16 22.7,54.61 20.15,57.15 20.15,63.5 18.88,64.77 13.17,64.77 11.9,63.5 X4.6
N$66
  Bottom 0.61: IC8.15 20.15,54.61 18.25,56.51 C33.1
PB4
  Top 0.305: IC3.14 40.48,32.7 40.48,38.1 44.92,42.54 44.92,44.45 K2.10
PB5
  Top 0.305: IC3.15 39.84,32.22 39.84,38.73 43.65,42.54 K2.7
PB6
  Top 0.305: IC3.16 39.2,31.74 39.2,39.37 42.38,42.54 42.38,44.45 K2.8
PD0  (via drill 0.6)
  Top 0.305: v43.65,19.68 43.65,20.42 IC3.25 | v37.94,32.38 38.57,33.02 38.57,40 41.11,42.54 K2.5
  Bottom 0.305: v43.65,19.68 41.11,19.68 37.94,22.86 v37.94,32.38
PD1  (via drill 0.6)
  Top 0.305: v44.92,18.41 44.92,20.58 IC3.26 | v36.66,31.11 36.66,33.02 37.94,34.29 37.94,40.64 39.84,42.54 39.84,44.45 K2.6
  Bottom 0.305: v44.92,18.41 40.48,18.41 36.66,22.22 v36.66,31.11
PDI  (via drill 0.6)
  Top 0.305: v48.73,40 48.09,39.37 48.09,38.44 IC3.2 | v34.76,40.64 33.49,39.37 33.49,36.83 K1.1
  Bottom 0.305: v34.76,40.64 48.09,40.64 v48.73,40
PDO  (via drill 0.6)
  Top 0.305: v46.82,38.73 46.82,38.6 IC3.3 | v36.03,39.37 36.03,41.27 35.39,41.91 30.95,41.91 K1.9
  Bottom 0.305: v36.03,39.37 46.19,39.37 v46.82,38.73
PF0
  Top 0.305: IC3.61 55.08,37.42 55.08,38.73 51.27,42.54 K2.13
PF1
  Top 0.305: IC3.60 55.71,36.94 55.71,39.37 52.54,42.54 52.54,44.45 K2.14
PF2
  Top 0.305: IC3.59 56.35,36.46 56.35,40 53.81,42.54 K2.15
PF3
  Top 0.305: IC3.58 56.98,35.98 56.98,40.64 55.08,42.54 55.08,44.45 K2.16
PF4
  Top 0.305: IC3.57 57.62,35.51 57.62,41.27 56.98,41.91 56.98,42.54 K2.17
PF5
  Top 0.305: IC3.56 58.25,35.03 58.25,41.91 57.62,42.54 57.62,44.45 K2.18
PF6
  Top 0.305: IC3.55 58.89,34.55 K2.19
PF7
  Top 0.305: IC3.54 60.16,34.71 60.16,44.45 K2.20
RD  (via drill 0.6)
  Top 0.305: IC3.34 58.1,13.97 60.8,13.97 62.7,15.87 62.7,19.68 62.06,20.31 v60.16,20.31
  Bottom 0.305: IC5.24 62.53,29.04 60.16,26.66 v60.16,20.31
RST  (via drill 0.6)
  Top 0.305: IC3.20 41.78,24.12 37.94,24.12 | 37.94,24.12 R3.1 | 37.94,24.12 35.81,24.12 C16.2 35.39,24.12 v32.22,24.12 32.22,13.33 32.38,13.17 S1.3 32.22,12.88 32.22,12.7 24.78,12.7 S1.4
  Bottom 0.305: K1.5 28.41,36.83 28.41,27.93 v32.22,24.12
RXD  (via drill 0.6)
  Top 0.305: R21.1 68.41,45.08 68,45.5 68,46.98 | 68,46.98 IC6.1 | IC3.27 46.19,20.74 46.19,17.14 48.73,14.6 50,14.6 56.98,7.62 66.51,7.62 76.67,17.77 v76.67,45.08 | v68.41,46.98 68,46.98
  Bottom 0.305: v68.41,46.98 74.77,46.98 v76.67,45.08
SCK  (via drill 0.6)
  Top 0.305: IC7.8 v23.96,29.2 | IC3.11 42.38,34.14 42.38,36.19 48.73,42.54 K2.11 | v51.27,55.24 v51.27,57.78 51.27,66.67 R16.1
  Bottom 0.305: K1.7 28.41,41.91 28.41,45.08 | 28.41,45.08 28.41,48.89 37.3,57.78 v51.27,57.78 | v23.96,29.2 23.96,34.29 25.23,35.55 25.23,43.81 26.5,45.08 28.41,45.08 | K2.11 50,44.45 50,49.53 52.54,52.07 52.54,53.97 v51.27,55.24
SCK_3V3
  Top 0.305: X3.5 47.46,63.5 49.37,65.4 49.37,66.67 | 49.37,66.67 R16.2 | R17.1 49.37,68.89 49.37,66.67
SD_AVAIL  (via drill 0.6)
  Top 0.305: IC3.32 49.76,18.65 56.98,11.43 64.61,11.43 72.86,19.68 72.86,39.37 71.59,40.64 67.78,40.64 62.7,45.72 v62.7,49.53 X3.CARD_DETECT
  Bottom 0.305: v62.7,49.53 R28.1
SD_WP
  Top 0.305: IC3.31 48.09,18.19 48.09,17.77 48.73,17.14 50,17.14 56.98,10.16 65.24,10.16 74.13,19.04 74.13,40.64 72.86,41.91 68.41,41.91 64.61,45.72 64.61,59.05 57.77,65.88 X3.CARD_WP
SS_NET  (via drill 0.6)
  Top 0.305: IC3.10 43.65,33.98 v43.65,35.55 | v36.03,35.55 36.03,34.29 32.22,30.47 IC7.9
  Bottom 0.305: v36.03,35.55 v43.65,35.55
SS_SD  (via drill 0.6)
  Top 0.305: IC3.17 40.98,26.66 v32.22,26.66 | T1.1 46.51,68.26 46.82,68.57 | 46.82,65.4 R1.1
  Top 0.406: R1.1 46.82,68.57 | v46.19,56.51 46.19,64.77 46.82,65.4
  Bottom 0.305: v32.22,26.66 30.95,27.93 30.95,49.53 37.94,56.51 v46.19,56.51 58.89,56.51 60.16,57.78 R27.1 60.16,61.59
SS_SD_3V3  (via drill 0.6)
  Top 0.305: X3.1 v37.3,64.13 | T1.3 43.02,68.74 43.02,66.67 | 43.02,66.67 R18.2 | v42.38,64.13 43.02,64.77 43.02,66.67
  Bottom 0.305: v37.3,64.13 v42.38,64.13
TXD
  Top 0.305: IC6.5 70.6,47.34 71.59,46.35 74.13,46.35 74.34,46.14 R22.1 75.4,44.03 75.4,18.41 65.88,8.89 56.98,8.89 55.71,10.16 | 55.71,10.16 55.65,10.22 | IC3.28 46.82,20.26 46.82,17.77 48.73,15.87 50,15.87 55.71,10.16
VCC  (via drill 0.6)
  Top 0.305: IC6.4 69.95,45.35 69.69,45.08 R21.2 R22.2 72.86,45.08 72.86,43.81 v73.5,43.18 | C21.1 76.03,50.8 73.2,53.63 IC6.20 73.2,58.08 v72.22,59.05 70.32,59.05 C20.1 | IC3.52 62.6,34.92 63.97,34.92 64.82,35.77 C5.1 64.82,39.15 v63.34,40.64 | 37.94,21.58 R3.2 | IC3.21 40.36,21.58 37.94,21.58 | 37.94,19.68 37.94,21.58 | 37.94,19.68 C4.1 | 37.94,19.68 37.94,19.04 v36.66,17.77
  Top 0.61: 88.1,45.72 89.37,44.45 IC1.2 | 88.1,45.72 R7.2 | 88.1,45.72 87.94,45.88 83.02,45.88 | 83.02,45.88 80.64,45.88 80.48,45.72 C3.+ | IC2.3 v84.92,19.04 84.92,22 C10.1 | v83.02,48.26 83.02,45.88 | K1.2 25.23,34.92 25.23,43.81 27.77,46.35 35.39,46.35 K2.2
  Bottom 0.305: LED4.A LED3.A 81.11,57.78 | 81.11,57.78 81.11,50.16 v83.02,48.26 | 81.11,57.78 72.22,57.78 | 72.22,57.78 67.78,57.78 65.24,60.32 65.24,64.13 LED8.A LED7.A | 72.22,57.78 v72.22,59.05 | IC5.32 66.68,18.88 66.51,19.04 66.51,20.95 66.97,21.41 IC5.30 72.69,21.41 | v63.34,40.64 L1.1 | IC4.20 51.06,22.01 49.37,20.31 49.37,17.14
  Bottom 0.406: 72.86,21.58 72.69,21.41
  Bottom 0.61: 84.92,24.12 v84.92,19.04 | 84.92,24.12 84.92,29.84 | 84.92,29.84 LED5.A | 84.92,29.84 84.92,43.18 | 84.92,43.18 84.92,46.35 v83.02,48.26 | K1.2 27.14,27.3 v36.66,17.77 37.3,17.14 49.37,17.14 51.27,17.14 56.98,11.43 64.61,11.43 72.86,19.68 72.86,21.58 75.4,24.12 84.92,24.12 | 84.92,43.18 v73.5,43.18 65.88,43.18 v63.34,40.64
WR  (via drill 0.6)
  Top 0.305: IC3.33 58.25,12.7 v60.16,12.7
  Bottom 0.305: 68.25,22.68 IC5.29 66.34,22.68 65.24,21.58 65.24,15.24 62.7,12.7 v60.16,12.7

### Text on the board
Top: mega-eth rev 1.1 (c) 2008 R. Riegel
Bottom: mega-eth rev 1.1 (c) 2008 R. Riegel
